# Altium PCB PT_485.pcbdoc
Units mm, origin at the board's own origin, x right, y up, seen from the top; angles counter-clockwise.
Board outline 61.6 x 60 mm, 2 copper layers (Top Layer, Bottom Layer); 37 components, 24 nets, 93 pads, 62 vias.
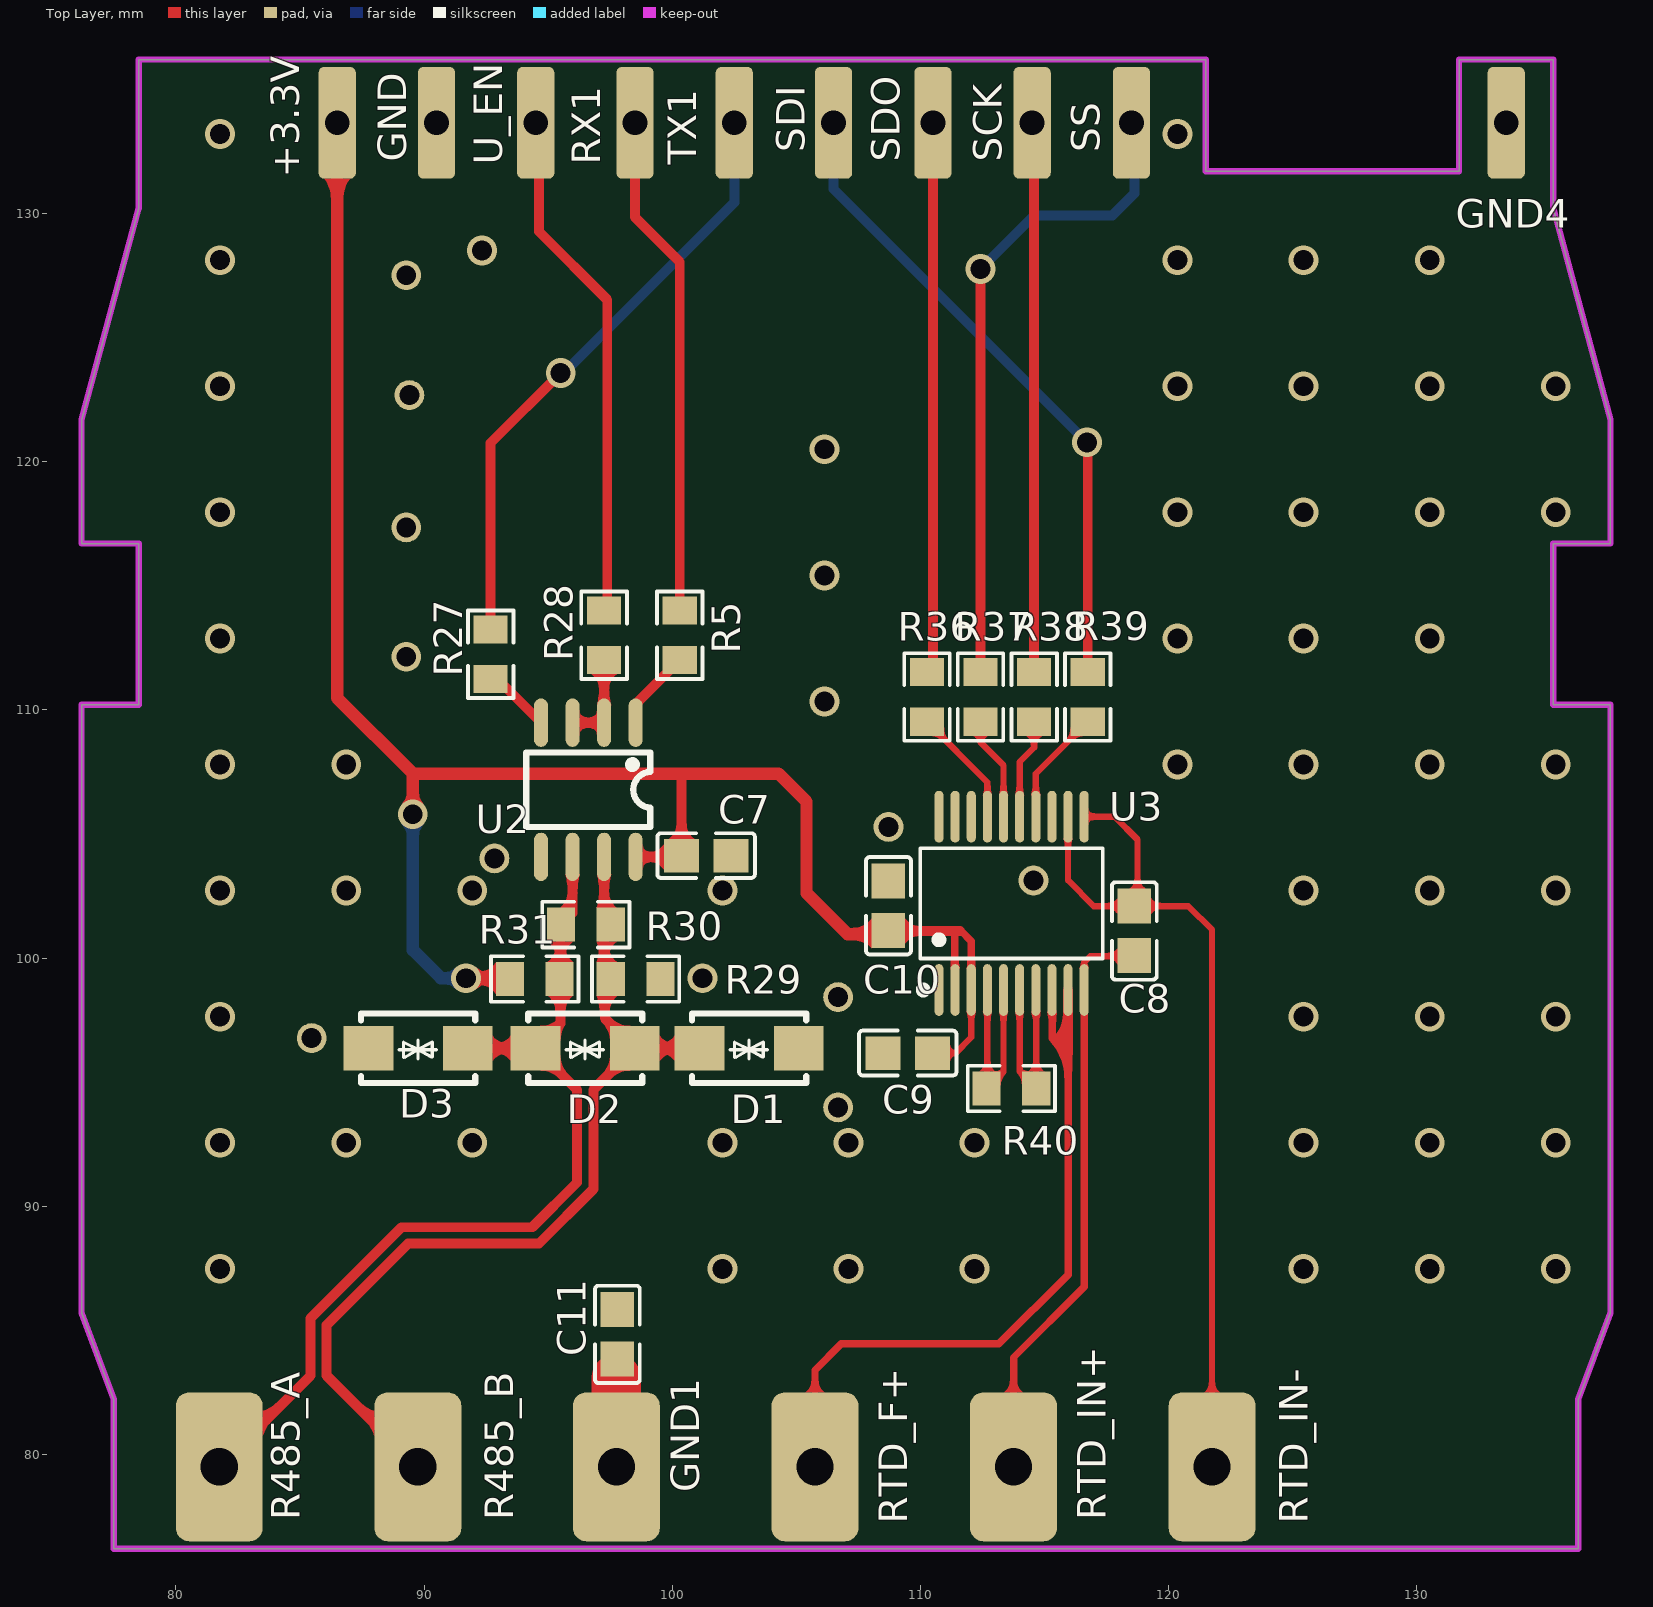
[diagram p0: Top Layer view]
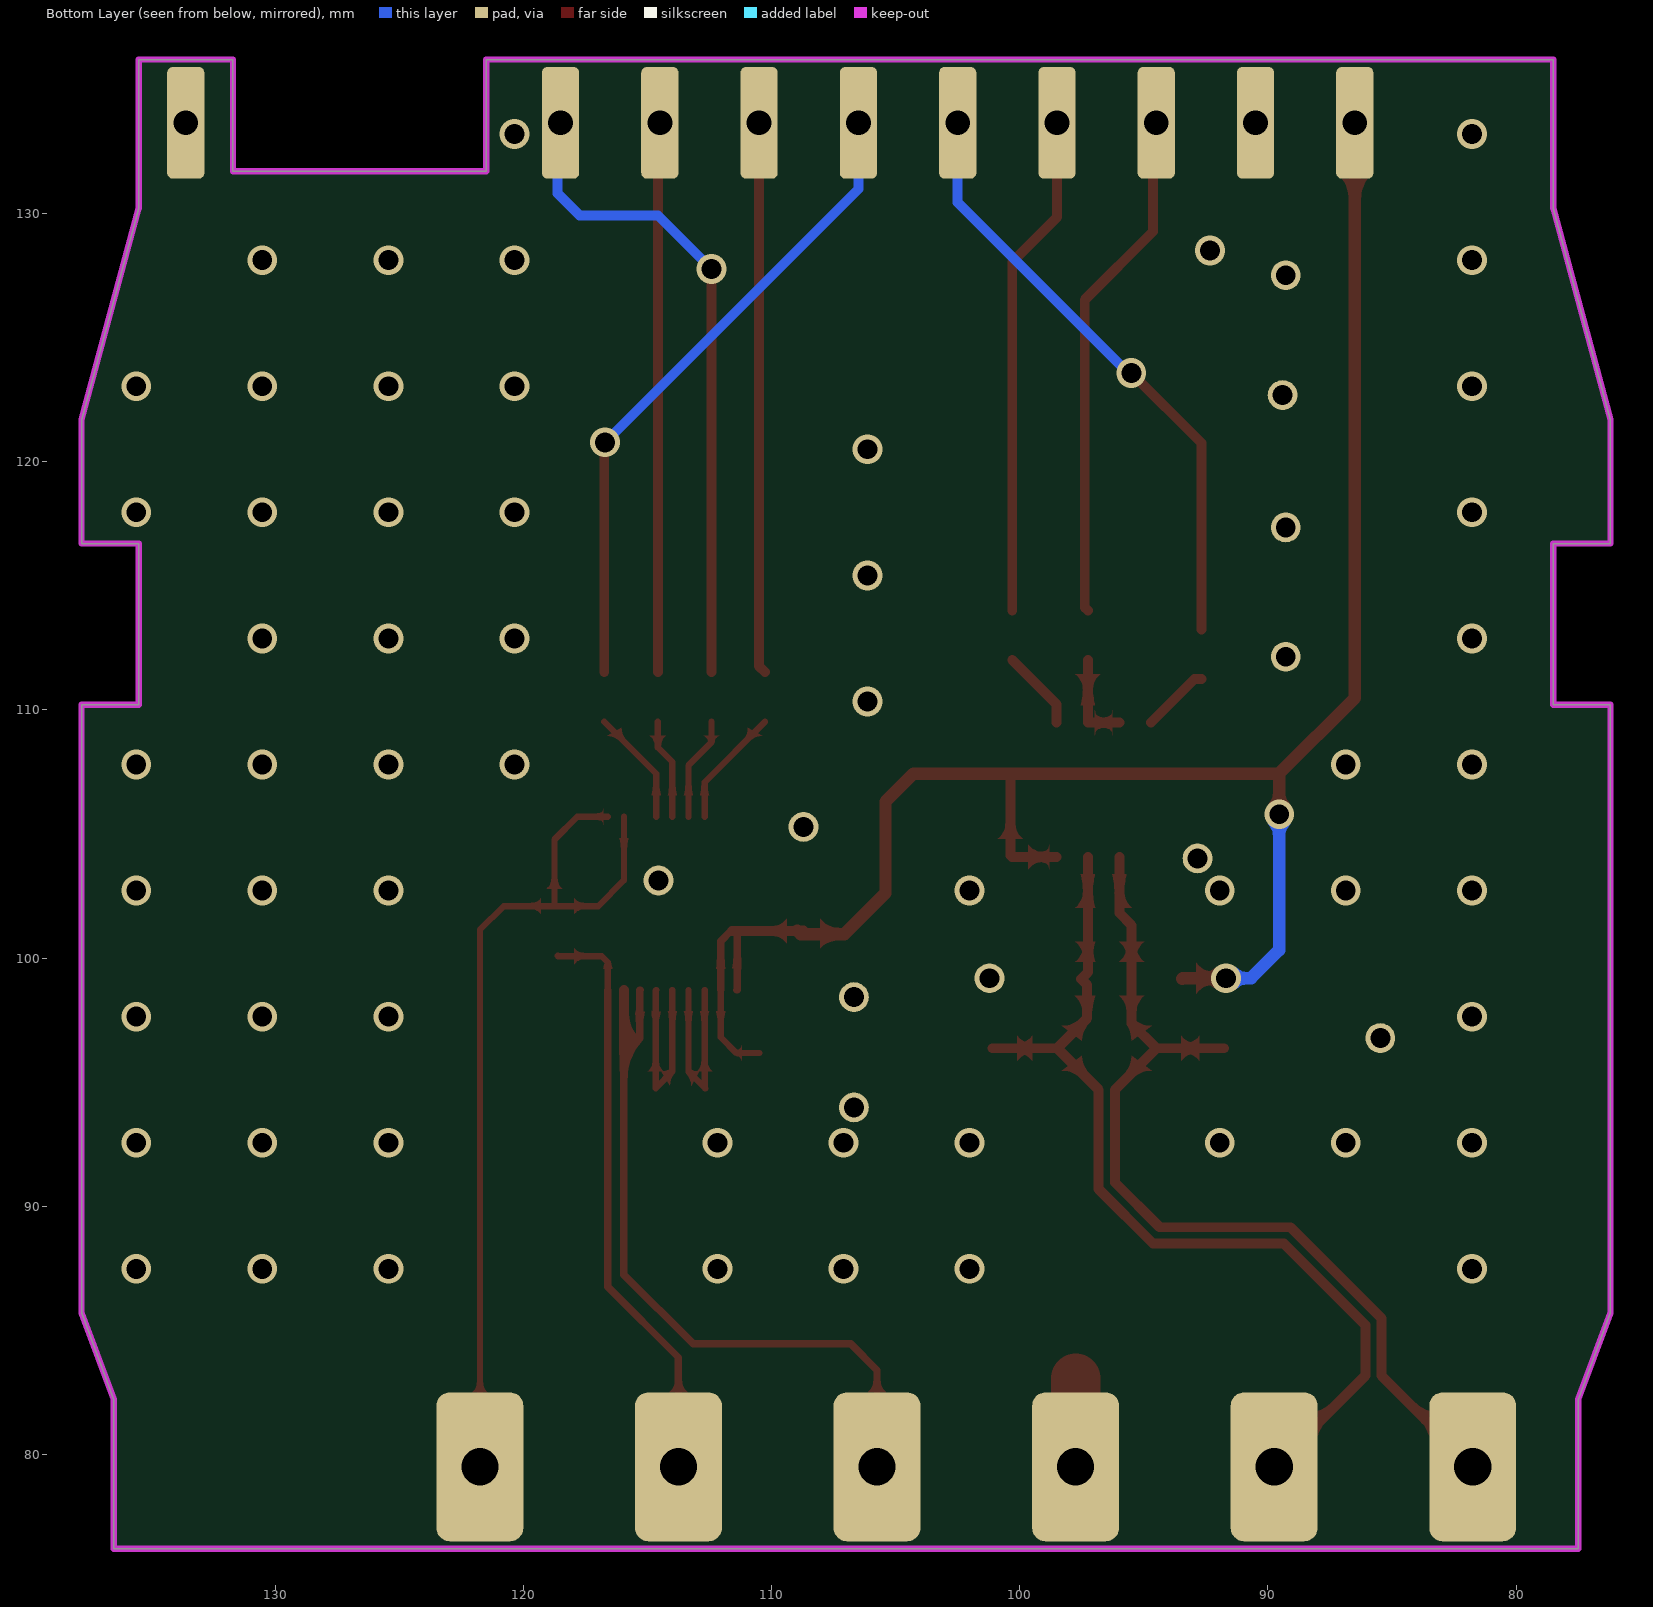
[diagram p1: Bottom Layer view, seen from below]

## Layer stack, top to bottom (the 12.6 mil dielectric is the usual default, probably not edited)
Top Layer: signal copper (thickness not stored)
Dielectric: dielectric 0.32, FR-4, Dk 4.8
Bottom Layer: signal copper (thickness not stored)

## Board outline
121.5,136.2 78.5,136.2 78.5,130.2 76.2,121.7 76.2,116.7 78.5,116.7 78.5,110.2 76.2,110.2 76.2,85.7 77.5,82.2 77.5,76.2 136.5,76.2 136.5,82.2 137.8,85.7 137.8,110.2 135.5,110.2 135.5,116.7 137.8,116.7 137.8,121.7 135.5,130.2 135.5,136.2 131.7,136.2 131.7,131.7 121.5,131.7

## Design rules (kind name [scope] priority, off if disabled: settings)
BoardOutlineClearance copperThickness1oz [All] p0: genericclearance=0.254 ignorepadtopadclearanceinfootprint=FALSE except(0: Arc-SplitContinuation Track-SplitContinuation SMDPad-SplitContinuation THPad-SplitContinuation Via-SplitContinuation Fill-SplitContinuation Poly-SplitContinuation Region-SplitContinuation Text-SplitContinuation; 0.203: SMDPad-OutlineEdge THPad-OutlineEdge Via-OutlineEdge; 0.254: Track-CutoutEdge SMDPad-CutoutEdge THPad-CutoutEdge Via-CutoutEdge Fill-CutoutEdge Region-CutoutEdge; 0.305: Track-OutlineEdge Fill-OutlineEdge Region-OutlineEdge Poly-OutlineEdge Text-OutlineEdge)
BoardOutlineClearance copperThickness2oz [All] p0: genericclearance=0.254 ignorepadtopadclearanceinfootprint=FALSE except(0: Arc-SplitContinuation Track-SplitContinuation SMDPad-SplitContinuation THPad-SplitContinuation Via-SplitContinuation Fill-SplitContinuation Poly-SplitContinuation Region-SplitContinuation Text-SplitContinuation; 0.152: Track-CutoutEdge SMDPad-CutoutEdge THPad-CutoutEdge Via-CutoutEdge Region-CutoutEdge; 0.3: Track-OutlineEdge SMDPad-OutlineEdge THPad-OutlineEdge Via-OutlineEdge Fill-OutlineEdge Region-OutlineEdge Poly-OutlineEdge Text-OutlineEdge Fill-CutoutEdge)
Clearance copperThickness1oz [(InNet('+3.3V') OR InNet('GND') OR InNet('RTD_IN+') OR InNet('R485_B') OR InNet('R485_A') OR InNet('$3N638') OR InNet('U1_RX') OR InNet('$3N640') OR InNet('U1_TX') OR InNet('$3N639') OR InNet('U1_EN') OR InNet('$2N377') OR InNet('SDO') OR InNet('$2N381') OR InNet('SS') OR InNet('$2N386') OR InNet('SCLK') OR InNet('$2N391') OR InNet('SDI') OR InNet('$2N592') OR InNet('$2N609') OR InNet('RTD_F+') OR InNet('RTD_F-') OR InNet('GND1'))] p1: gap=0.178 ignorepadtopadclearanceinfootprint=FALSE except(0.203: SMDPad-Sheet THPad-Sheet Via-Sheet; 0.254: Track-Track Track-SMDPad SMDPad-SMDPad Track-THPad SMDPad-THPad THPad-THPad Track-Via SMDPad-Via THPad-Via Via-Via SMDPad-Fill THPad-Fill Via-Fill Fill-Fill Track-Region SMDPad-Region THPad-Region Via-Region Fill-Region Region-Region Track-Poly SMDPad-Poly THPad-Poly Via-Poly Fill-Poly Region-Poly Poly-Poly Track-Text SMDPad-Text THPad-Text Via-Text Fill-Text Region-Text Poly-Text Text-Text Track-Hole SMDPad-Hole THPad-Hole Via-Hole Fill-Hole Region-Hole Poly-Hole Text-Hole Sheet-Hole; 0.305: Track-Fill Track-Sheet Fill-Sheet Region-Sheet Poly-Sheet Text-Sheet)
Clearance copperThickness2oz [All] p1: gap=0.178 ignorepadtopadclearanceinfootprint=FALSE except(0.152: Track-SMDPad SMDPad-SMDPad Track-THPad SMDPad-THPad THPad-THPad Track-Via SMDPad-Via THPad-Via Via-Via SMDPad-Fill THPad-Fill Via-Fill Fill-Fill Track-Region SMDPad-Region THPad-Region Via-Region Region-Region Track-Poly SMDPad-Poly THPad-Poly Via-Poly Fill-Poly Region-Poly Poly-Poly Track-Text SMDPad-Text THPad-Text Via-Text Fill-Text Region-Text Poly-Text Text-Text; 0.175: Track-Hole SMDPad-Hole THPad-Hole Via-Hole Fill-Hole Region-Hole Poly-Hole Text-Hole Sheet-Hole; 0.203: Track-Track; 0.3: Track-Fill Fill-Region Track-Sheet SMDPad-Sheet THPad-Sheet Via-Sheet Fill-Sheet Region-Sheet Poly-Sheet Text-Sheet)
DiffPairsRouting differentialPair [All] p1: maxuncoupledlength=10 minlimit=10 maxlimit=10 mostfreqgap=10 toplayer_minwidth=10 toplayer_prefwidth=15.748 toplayer_maxwidth=100 bottomlayer_minwidth=10 bottomlayer_prefwidth=15.748 bottomlayer_maxwidth=100
PasteMaskExpansion pasteMaskExpansion [All] p1: expansion=0
PlaneConnect innerPlane [All] p1: planeconnectstyle=Relief reliefexpansion=0.508 reliefentries=4 reliefconductorwidth=0.254 reliefairgap=0.254
PolygonConnect copperRegion [All] p1: connectstyle=Direct reliefentries=4 reliefconductorwidth=10 polygonreliefangle="90 Angle" airgapwidth=10
RoutingVias viaSize [All] p1: viastyle="Through Hole" holewidth=31.496 minholewidth=11.811 maxholewidth=247.9922 width=47.244 minwidth=19.685 maxwidth=393.7008
SolderMaskExpansion solderMaskExpansion [All] p1: useseparateexpansions=TRUE expansion=2.0079 expansionbottom=2.0079
Width copperThickness1oz [All] p1: maxlimit=100 minlimit=5 preferedwidth=10
Width copperThickness2oz [All] p1: maxlimit=100 minlimit=8 preferedwidth=10

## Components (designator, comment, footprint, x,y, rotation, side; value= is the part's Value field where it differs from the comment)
+3.3V "S_TM" S_FT 86.5,133.65 r0 top
C7 "CC0805KRX7R9BB104" C0805 101.366,104.128 r180 top
C8 "CC0805KRX7R9BB104" C0805 118.618,101.092 r90 top
C9 "CC0805KRX7R9BB104" C0805 109.49,96.171 r180 top
C10 "CC0805KRX7R9BB104" C0805 108.712,102.108 r90 top
C11 "0805B102K102CT" C0805 97.79,84.836 r90 top
D1 "SMAJ12CA_C152122" SMA_L4.4-W2.6-LS5.0-BI 103.096,96.365 r0 top
D2 "SMAJ12CA_C152122" SMA_L4.4-W2.6-LS5.0-BI 96.492,96.365 r0 top
D3 "SMAJ12CA_C152122" SMA_L4.4-W2.6-LS5.0-BI 89.761,96.365 r0 top
GND "S_TM" S_FT 90.5,133.65 r0 top
GND1 "B_TM" B_FT 97.75,79.5 r180 top
GND4 "S_TM" S_FT 133.6,133.65 r180 top
R5 "RC0805FR-071KL" R0805 100.302,113.002 r270 top
R27 "RC0805FR-071KL" R0805 92.682,112.24 r270 top
R28 "RC0805FR-071KL" R0805 97.254,113.002 r270 top
R29 "RC0805FR-074K7L" R0805 98.524,99.159 r0 top
R30 "RC0805FR-07120RL" R0805 96.52,101.346 r0 top
R31 "RC0805FR-074K7L" R0805 94.46,99.159 r0 top
R36 "RC0805JR-070RL" R0805 110.263,110.518 r270 top
R37 "RC0805JR-070RL" R0805 112.422,110.518 r270 top
R38 "RC0805JR-070RL" R0805 114.581,110.518 r270 top
R39 "RC0805JR-070RL" R0805 116.74,110.518 r270 top
R40 "TR0805B400RP0525Z" R0805 113.665,94.742 r180 top
R485_A "B_TM" B_FT 81.75,79.5 r180 top
R485_B "B_TM" B_FT 89.75,79.5 r180 top
RTD_F+ "B_TM" B_FT 105.75,79.5 r180 top
RTD_IN+ "B_TM" B_FT 113.75,79.5 r180 top
RTD_IN- "B_TM" B_FT 121.75,79.5 r180 top
RX1 "S_TM" S_FT 98.5,133.65 r180 top
SCK "S_TM" S_FT 114.5,133.65 r180 top
SDI "S_TM" S_FT 106.5,133.65 r180 top
SDO "S_TM" S_FT 110.5,133.65 r180 top
SS "S_TM" S_FT 118.5,133.65 r180 top
TX1 "S_TM" S_FT 102.5,133.65 r180 top
U2 "SP3485EN-L/TR" SOIC-8_L5.0-W4.0-P1.27-LS6.0-BL 96.619,106.779 r180 top
U3 "MAX31865AAP+T" SSOP-20_L7.2-W5.3-P0.65-LS7.8-BL 113.672,102.204 r0 top
U_EN "S_TM" S_FT 94.5,133.65 r180 top

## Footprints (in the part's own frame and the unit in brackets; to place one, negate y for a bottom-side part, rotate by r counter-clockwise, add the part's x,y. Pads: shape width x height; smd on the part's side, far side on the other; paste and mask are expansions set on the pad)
B_FT [mm]
  rrect30% 3.5x6 hole 1.5: 1(0,0)
C0805 [mm]
  rect 1.41x1.35 smd: 1(-1,0) 2(1,0)
  silkscreen extent -1.96,-0.9 1.96,0.9
R0805 [mm]
  rect 1.133x1.377 smd: 1(-1,0) 2(1,0)
  silkscreen extent -1.76,-0.92 1.76,0.92
S_FT [mm]
  rrect30% 1.5x4.5 hole 1: 1(0,0)
SMA_L4.4-W2.6-LS5.0-BI [mm]
  rect 2x1.8 smd: 1(-2,0) 2(2,0)
  silkscreen extent -2.3,-1.4 2.3,1.4
SOIC-8_L5.0-W4.0-P1.27-LS6.0-BL [mil]
  oval 22.38x76.78 smd: 1(-75,-106.5) 2(-25,-106.5) 3(25,-106.5) 4(75,-106.5) 5(75,106.5) 6(25,106.5) 7(-25,106.5) 8(-75,106.5)
  silkscreen extent -98,-59 98,59
SSOP-20_L7.2-W5.3-P0.65-LS7.8-BL [mm]
  oval 0.364x2.082 smd: 1(-2.925,-3.491) 2(-2.275,-3.491) 3(-1.625,-3.491) 4(-0.975,-3.491) 5(-0.325,-3.491) 6(0.325,-3.491) 7(0.975,-3.491) 8(1.625,-3.491) 9(2.275,-3.491) 10(2.925,-3.491) 11(2.925,3.491) 12(2.275,3.491) 13(1.625,3.491) 14(0.975,3.491) 15(0.325,3.491) 16(-0.325,3.491) 17(-0.975,3.491) 18(-1.625,3.491) 19(-2.275,3.491) 20(-2.925,3.491)
  silkscreen extent -3.71,-3.64 3.68,2.22

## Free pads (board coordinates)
  round 1.2 hole 0.8: 1(85.471,96.774) 1(89.281,112.141) 1(89.281,117.348) 1(89.281,127.508) 1(89.408,122.682) 1(92.837,104.013) 1(101.219,99.187) 1(106.68,93.98) 1(106.68,98.425) 1(108.712,105.283) 1(114.554,103.124)

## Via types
v1: diameter 1.2, hole 0.8, Top Layer to Bottom Layer, 62 vias

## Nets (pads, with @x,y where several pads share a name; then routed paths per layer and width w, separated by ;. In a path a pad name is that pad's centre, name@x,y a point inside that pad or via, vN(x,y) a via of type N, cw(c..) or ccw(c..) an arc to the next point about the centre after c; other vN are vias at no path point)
$2N377: R36.2 U3.17 | length 4.8
  Top Layer w0.254: R36.2 112.696,107.084 U3.17
$2N381: R37.2 U3.16 | length 4.2
  Top Layer w0.254: R37.2 112.422,108.685 113.347,107.76 U3.16
$2N386: R38.2 U3.15 | length 4.1
  Top Layer w0.254: U3.15 113.997,107.901 114.581,108.485 R38.2
$2N391: R39.2 U3.14 | length 4.7
  Top Layer w0.254: U3.14 114.647,107.425 R39.2
$2N592: R40.2 U3.4 U3.5 | length 8.2
  Top Layer w0.254: R40.2 R40.2@112.696,94.773 ; U3.4 R40.2@112.696,94.773 ; U3.5 113.347,95.424 R40.2@112.696,94.773
$2N609: R40.1 U3.6 U3.7 | length 8.2
  Top Layer w0.254: U3.6 113.997,95.426 114.665,94.758 114.665,98.694 U3.7
$3N638: R5.2 U2.1 | length 3.3
  Top Layer w0.4: U2.1 98.524,110.224 R5.2
$3N639: R28.2 U2.2 U2.3 | length 3.8
  Top Layer w0.4: U2.3 U2.2 R28.2
$3N640: R27.2 U2.4 | length 2.8
  Top Layer w0.4: R27.2 92.958,111.24 U2.4
+3.3V: +3.3V.1 C7.2 C9.1 C10.1 R31.1 U2.8 U3.2 U3.3 | length 80.1
  Top Layer w0.254: C9.1 111.411,96.171 112.046,96.806 U3.3
  Top Layer w0.3: 111.379,101.108 111.379,101.089 111.379,98.73 U3.2 ; 111.617,101.108 112.046,100.679 U3.3
  Top Layer w0.4: U2.8 100.312,104.074 C7.2 100.377,104.139 100.377,107.43 ; C10.1 108.966,101.108 108.985,101.089 111.379,101.089 111.598,101.089
  Top Layer w0.5: +3.3V.1 86.5,110.477 89.547,107.43 ; v1(89.547,105.791) 89.547,107.43 ; v1(91.694,99.187) 93.432,99.187 R31.1 ; C10.1@108.966,101.108 108.823,100.965 107.061,100.965 105.41,102.616 105.41,106.299 104.279,107.43 100.377,107.43 89.547,107.43
  Bottom Layer w0.5: v1(89.547,105.791) 89.547,100.318 90.678,99.187 v1(91.694,99.187)
GND: C7.1 C9.2 C10.2 C11.2 D1.2 D3.1 GND4.1 GND.1 pad.1 R29.2 U2.5 U3.13 U3.18 U3.19 U3.20
  other v1: 81.784,87.478 102.021,87.478 107.101,87.478 112.181,87.478 125.438,87.478 130.518,87.478 135.598,87.478 81.784,92.558 86.864,92.558 91.944,92.558 102.021,92.558 107.101,92.558 112.181,92.558 125.438,92.558 130.518,92.558 135.598,92.558 81.784,97.638 125.438,97.638 130.518,97.638 135.598,97.638 81.784,102.718 86.864,102.718 91.944,102.718 102.021,102.718 125.438,102.718 130.518,102.718 135.598,102.718 81.784,107.798 86.864,107.798 120.358,107.798 125.438,107.798 130.518,107.798 135.598,107.798 106.136,110.336 81.784,112.878 120.358,112.878 125.438,112.878 130.518,112.878 106.136,115.416 81.784,117.958 120.358,117.958 125.438,117.958 130.518,117.958 135.598,117.958 106.136,120.496 81.784,123.038 120.358,123.038 125.438,123.038 130.518,123.038 135.598,123.038 81.784,128.118 120.358,128.118 125.438,128.118 130.518,128.118 92.334,128.504 81.784,133.198 120.358,133.198
GND1: C11.1 GND1.1 | length 3.6
  Top Layer w2: GND1.1 97.75,83.058
R485_A: D2.1 D3.2 R30.1 R31.2 R485_A.1 U2.6 | length 37.7
  Top Layer w0.4: R485_A.1 85.423,83.173 85.423,85.488 89.089,89.154 94.361,89.154 96.165,90.958 96.165,94.692 D2.1 ; D3.2 D2.1 ; U2.6 95.984,101.81 95.492,101.318 95.492,97.365 D2.1
R485_B: D1.1 D2.2 R29.1 R30.2 R485_B.1 U2.7 | length 37.6
  Top Layer w0.4: R485_B.1 86.077,83.173 86.077,85.217 89.36,88.5 94.632,88.5 96.819,90.687 96.819,94.692 D2.2 ; U2.7 97.254,99.429 R29.1 97.282,98.917 97.282,97.575 D2.2 ; D1.1 D2.2
RTD_F+: RTD_F+.1 U3.8 U3.9 | length 30
  Top Layer w0.3: RTD_F+.1 105.75,83.398 106.807,84.455 113.157,84.455 115.947,87.245 115.947,96.143 115.316,96.774 115.316,98.693 U3.8
  Top Layer w0.4: 115.947,96.143 U3.9
RTD_F-: C8.2 RTD_IN-.1 U3.11 U3.12 | length 35.9
  Top Layer w0.254: U3.12 115.947,103.128 116.983,102.092 C8.2 120.793,102.092 121.75,101.135 RTD_IN-.1 ; U3.11 117.825,105.695 118.745,104.775 C8.2@118.745,102.235
RTD_IN+: C8.1 RTD_IN+.1 U3.10 | length 23.6
  Top Layer w0.254: U3.10 116.597,99.833 116.84,100.076 118.602,100.076 C8.1
  Top Layer w0.3: RTD_IN+.1 113.75,83.905 116.597,86.752 U3.10
SCLK: R38.1 SCK.1 | length 22.2
  Top Layer w0.4: SCK.1 114.581,133.569 R38.1
SDI: R39.1 SDI.1 | length 26.4
  Top Layer w0.4: v1(116.713,120.777) 116.74,120.75 R39.1
  Bottom Layer w0.4: SDI.1 106.5,130.99 v1(116.713,120.777)
SDO: R36.1 SDO.1 | length 22.2
  Top Layer w0.4: R36.1 110.5,111.755 SDO.1
SS: R37.1 SS.1 | length 26.6
  Top Layer w0.4: R37.1 v1(112.422,127.762)
  Bottom Layer w0.4: v1(112.422,127.762) 114.581,129.921 117.729,129.921 118.618,130.81 118.618,133.532 SS.1
U1_EN: R28.1 U_EN.1 | length 20.9
  Top Layer w0.4: U_EN.1 94.627,133.523 94.627,129.274 97.381,126.52 97.381,114.129 R28.1
U1_RX: R5.1 RX1.1 | length 20.4
  Top Layer w0.4: RX1.1 98.5,129.846 100.302,128.044 R5.1
U1_TX: R27.1 TX1.1 | length 24.6
  Top Layer w0.4: R27.1 92.682,120.749 v1(95.504,123.571)
  Bottom Layer w0.4: v1(95.504,123.571) 95.631,123.571 102.5,130.44 TX1.1
pads on no net: U3.1

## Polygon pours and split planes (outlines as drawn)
GND on Top Layer (solid, remove dead copper, pour order 0): 76.2,116.7 78.5,116.7 78.5,110.2 76.2,110.2 76.2,85.151 137.8,85.151 137.8,110.2 135.5,110.2 135.5,116.7 137.8,116.7 137.8,121.7 135.5,130.2 135.5,136.2 131.7,136.2 131.7,131.7 121.5,131.7 121.5,136.2 78.5,136.2 78.5,130.2 76.2,121.7
GND on Bottom Layer (solid, remove dead copper, pour order 2): 76.2,116.7 78.5,116.7 78.5,110.2 76.2,110.2 76.2,85.151 137.8,85.151 137.8,110.2 135.5,110.2 135.5,116.7 137.8,116.7 137.8,121.7 135.5,130.2 135.5,136.2 131.7,136.2 131.7,131.7 121.5,131.7 121.5,136.2 78.5,136.2 78.5,130.2 76.2,121.7

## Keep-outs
Board Outline Layer:
  the board outline again, w0.254

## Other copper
Top Layer:
  region net +3.3V: 86.75,130.65 86.25,130.65 ccw(c85.09,130.65) 85.975,131.4 87.025,131.4 ccw(c87.91,130.65)
  region net +3.3V: 100.177,105.403 100.577,105.403 ccw(c101.327,105.403) 100.877,104.803 99.877,104.803 ccw(c99.427,105.403)
  region net +3.3V: 99.061,103.874 99.061,104.274 ccw(c99.061,105.024) 99.661,104.574 99.661,103.574 ccw(c99.061,103.124)
  region net RTD_F-: 117.562,101.965 117.562,102.219 ccw(c117.562,102.695) 117.943,102.409 117.943,101.774 ccw(c117.562,101.489)
  region net RTD_F-: 118.618,103.178 118.872,103.178 ccw(c119.348,103.178) 119.062,102.797 118.427,102.797 ccw(c118.142,103.178)
  region net RTD_F-: 119.674,102.219 119.674,101.965 ccw(c119.674,101.489) 119.293,101.774 119.293,102.409 ccw(c119.674,102.695)
  region net RTD_IN+: 117.562,99.949 117.562,100.203 ccw(c117.562,100.679) 117.943,100.393 117.943,99.758 ccw(c117.562,99.473)
  region net +3.3V: 111.411,96.298 111.411,96.044 ccw(c111.411,95.826) 111.195,95.854 111.195,96.489 ccw(c111.411,96.516)
  region net +3.3V: 107.287,100.715 107.287,101.215 ccw(c107.287,102.152) 108.037,101.59 108.037,100.403 ccw(c107.287,99.658)
  region net +3.3V: 109.987,101.289 109.987,100.889 ccw(c109.987,100.139) 109.387,100.589 109.387,101.589 ccw(c109.987,102.039)
  region net R485_B: 99.496,96.165 99.496,96.565 ccw(c99.496,97.315) 100.096,96.865 100.096,95.865 ccw(c99.496,95.415)
  region net R485_A: 95.321,97.477 95.633,97.223 ccw(c96.694,96.658) 95.492,96.658 94.685,97.265 ccw(c94.685,98.325)
  region net R485_A: 95.704,95.436 95.321,95.253 ccw(c94.685,94.404) 94.685,95.465 95.492,96.072 ccw(c96.552,96.072)
  region net R485_A: 92.892,96.165 92.892,96.565 ccw(c92.892,97.315) 93.492,96.865 93.492,95.865 ccw(c92.892,95.415)
  region net R485_B: 97.28,97.294 97.663,97.477 ccw(c98.299,98.325) 98.299,97.265 97.492,96.658 ccw(c96.431,96.658)
  region net R485_B: 97.663,95.253 97.28,95.436 ccw(c96.431,96.072) 97.492,96.072 98.299,95.465 ccw(c98.299,94.404)
  region net R485_B: 100.092,96.565 100.092,96.165 ccw(c100.092,95.415) 99.492,95.865 99.492,96.865 ccw(c100.092,97.315)
  region net R485_A: 93.361,96.565 93.361,96.165 ccw(c93.361,95.415) 92.761,95.865 92.761,96.865 ccw(c93.361,97.315)
  region net $3N639: 97.454,110.836 97.054,110.836 ccw(c96.304,110.836) 96.754,111.436 97.754,111.436 ccw(c98.204,110.836)
  region net R485_B: 97.482,97.87 97.082,97.87 ccw(c95.573,97.87) 96.958,98.47 97.782,98.47 ccw(c98.232,97.87)
  region net R485_B: 97.054,100.447 97.454,100.447 ccw(c98.204,100.447) 97.754,99.847 96.958,99.847 ccw(c95.136,100.447)
  region net R485_B: 97.054,102.635 97.454,102.635 ccw(c98.204,102.635) 97.754,102.035 96.954,102.035 ccw(c95.206,102.635)
  region net R485_B: 97.454,100.057 97.054,100.057 ccw(c95.206,100.057) 96.954,100.657 97.754,100.657 ccw(c98.204,100.057)
  region net R485_A: 95.692,100.057 95.292,100.057 ccw(c94.542,100.057) 94.992,100.657 95.992,100.657 ccw(c96.442,100.057)
  region net R485_A: 95.784,102.635 96.184,102.635 ccw(c97.98,102.035) 96.086,102.035 95.484,102.035 ccw(c95.034,102.635)
  region net R485_A: 95.692,97.87 95.292,97.87 ccw(c94.542,97.87) 94.992,98.47 95.992,98.47 ccw(c96.442,97.87)
  region net R485_A: 95.292,100.447 95.692,100.447 ccw(c96.442,100.447) 95.992,99.847 94.992,99.847 ccw(c94.542,100.447)
  region net +3.3V: 92.144,98.937 92.144,99.437 ccw(c92.144,100.374) 92.894,99.812 92.894,98.562 ccw(c92.144,98)
  region net $2N377: 111.086,108.874 110.784,108.817 ccw(c110.38,108.278) 110.38,108.951 110.951,109.278 ccw(c111.625,109.278)
  region net $2N381: 112.549,108.685 112.295,108.685 ccw(c112.014,108.685) 112.104,108.951 112.739,108.951 ccw(c112.829,108.685)
  region net $2N386: 114.708,108.57 114.454,108.57 ccw(c113.977,108.57) 114.263,108.951 114.898,108.951 ccw(c115.184,108.57)
  region net $2N391: 116.218,108.817 115.916,108.874 ccw(c115.378,109.278) 116.051,109.278 116.622,108.951 ccw(c116.622,108.278)
  region net $2N592: 112.569,95.812 112.823,95.812 ccw(c113.3,95.812) 113.014,95.431 112.379,95.431 ccw(c112.093,95.812)
  region net $2N592: 113.257,95.513 113.366,95.263 ccw(c113.905,94.859) 113.231,94.859 112.904,95.431 ccw(c112.904,96.22)
  region net $2N609: 114.538,95.812 114.792,95.812 ccw(c115.268,95.812) 114.982,95.431 114.347,95.431 ccw(c114.062,95.812)
  region net $2N609: 113.964,95.279 114.086,95.516 ccw(c114.442,96.209) 114.442,95.431 114.099,94.875 ccw(c113.425,94.875)
  region net R485_A: 84.033,82.066 83.816,81.283 ccw(c84.699,80.4) 83.5,80.75 83.5,81.75 ccw(c83.15,82.949)
  region net R485_B: 87.684,81.283 87.467,82.066 ccw(c88.35,82.949) 88,81.75 88,80.75 ccw(c86.801,80.4)
  region net RTD_F+: 105.6,82.95 105.9,82.95 ccw(c106.462,82.95) 106.125,82.5 105.375,82.5 ccw(c105.038,82.95)
  region net RTD_IN+: 113.6,82.95 113.9,82.95 ccw(c114.462,82.95) 114.125,82.5 113.375,82.5 ccw(c113.038,82.95)
  region net RTD_F-: 121.623,82.881 121.877,82.881 ccw(c122.353,82.881) 122.068,82.5 121.433,82.5 ccw(c121.147,82.881)
  region net $3N639: 96.37,109.284 96.37,109.684 96.482,109.685 96.59,109.689 96.691,109.7 96.738,109.709 96.782,109.721 96.822,109.737 96.859,109.757 96.891,109.781 96.918,109.81 96.94,109.845 96.956,109.885 96.966,109.931 96.97,109.984 96.97,108.984 96.966,109.037 96.956,109.083 96.94,109.123 96.918,109.157 96.891,109.186 96.859,109.211 96.822,109.231 96.782,109.246 96.738,109.259 96.691,109.268 96.59,109.279 96.482,109.283
  region net $3N639: 97.054,110.775 97.454,110.775 97.457,110.664 97.467,110.558 97.48,110.46 97.496,110.372 97.525,110.237 97.538,110.175 96.97,110.175 96.983,110.237 97.012,110.372 97.027,110.46 97.041,110.558 97.05,110.664
  region net $3N639: 96.868,109.684 96.868,109.284 96.756,109.283 96.648,109.279 96.546,109.268 96.499,109.259 96.456,109.246 96.415,109.231 96.379,109.211 96.347,109.186 96.32,109.157 96.298,109.123 96.282,109.083 96.271,109.037 96.268,108.984 96.268,109.984 96.271,109.931 96.282,109.885 96.298,109.845 96.32,109.81 96.347,109.781 96.379,109.757 96.415,109.737 96.456,109.721 96.499,109.709 96.546,109.7 96.648,109.689 96.756,109.685
  region net +3.3V: 99.408,104.274 99.408,103.874 99.296,103.873 99.188,103.869 99.086,103.858 99.039,103.849 98.996,103.836 98.955,103.82 98.919,103.8 98.887,103.776 98.86,103.747 98.838,103.713 98.822,103.673 98.811,103.627 98.808,103.574 98.808,104.574 98.811,104.521 98.822,104.475 98.838,104.435 98.86,104.4 98.887,104.371 98.919,104.347 98.955,104.327 98.996,104.311 99.039,104.299 99.086,104.29 99.188,104.278 99.296,104.274
  region net R485_B: 97.454,102.783 97.054,102.783 97.05,102.894 97.041,103 97.027,103.098 97.012,103.186 96.983,103.321 96.97,103.383 97.538,103.383 97.525,103.321 97.496,103.186 97.48,103.098 97.467,103 97.457,102.894
  region net R485_A: 96.184,102.783 95.784,102.783 95.78,102.894 95.771,103 95.757,103.098 95.742,103.186 95.713,103.321 95.7,103.383 96.268,103.383 96.255,103.321 96.226,103.186 96.21,103.098 96.197,103 96.187,102.894
  region net +3.3V: 111.229,100.004 111.529,100.039 111.535,99.933 111.549,99.814 111.578,99.589 111.215,99.554 111.211,99.666 111.217,99.779 111.225,99.892
  region net +3.3V: 112.173,97.473 111.919,97.473 111.917,97.543 111.911,97.609 111.892,97.725 111.873,97.81 111.864,97.854 112.228,97.854 112.22,97.81 112.201,97.725 112.182,97.609 112.176,97.543
  region net +3.3V: 111.896,100.022 112.196,100.022 112.201,99.86 112.212,99.722 112.228,99.572 111.864,99.572 111.88,99.722 111.891,99.86
  region net $2N592: 112.823,97.473 112.569,97.473 112.567,97.543 112.561,97.609 112.542,97.725 112.523,97.81 112.514,97.854 112.878,97.854 112.87,97.81 112.851,97.725 112.832,97.609 112.826,97.543
  region net $2N592: 113.474,97.473 113.22,97.473 113.217,97.543 113.211,97.609 113.192,97.725 113.173,97.81 113.165,97.854 113.529,97.854 113.52,97.81 113.501,97.725 113.482,97.609 113.476,97.543
  region net $2N609: 114.124,97.473 113.87,97.473 113.867,97.543 113.861,97.609 113.842,97.725 113.823,97.81 113.815,97.854 114.179,97.854 114.17,97.81 114.151,97.725 114.132,97.609 114.126,97.543
  region net $2N609: 114.792,97.491 114.538,97.454 114.536,97.515 114.529,97.565 114.509,97.645 114.485,97.726 114.474,97.775 114.466,97.835 114.828,97.872 114.832,97.811 114.83,97.761 114.817,97.682 114.8,97.602 114.794,97.553
  region net RTD_F+: 115.466,97.423 115.166,97.384 115.16,97.488 115.146,97.61 115.116,97.834 115.478,97.873 115.482,97.764 115.477,97.648 115.47,97.533
  region net RTD_IN+: 116.47,99.833 116.724,99.833 116.726,99.785 116.732,99.74 116.751,99.663 116.77,99.605 116.779,99.572 116.415,99.572 116.423,99.605 116.442,99.663 116.461,99.74 116.467,99.785
  region net $2N377: 112.569,106.935 112.823,106.935 112.826,106.865 112.832,106.798 112.851,106.682 112.87,106.597 112.878,106.554 112.514,106.554 112.523,106.597 112.542,106.682 112.561,106.798 112.567,106.865
  region net $2N381: 113.22,106.935 113.474,106.935 113.476,106.865 113.482,106.798 113.501,106.682 113.52,106.597 113.529,106.554 113.165,106.554 113.173,106.597 113.192,106.682 113.211,106.798 113.217,106.865
  region net $2N386: 113.87,106.935 114.124,106.935 114.126,106.865 114.132,106.798 114.151,106.682 114.17,106.597 114.179,106.554 113.815,106.554 113.823,106.597 113.842,106.682 113.861,106.798 113.867,106.865
  region net $2N391: 114.52,106.935 114.774,106.935 114.776,106.865 114.782,106.798 114.801,106.682 114.82,106.597 114.829,106.554 114.465,106.554 114.473,106.597 114.492,106.682 114.511,106.798 114.517,106.865
  region net RTD_F-: 116.074,104.455 115.82,104.455 115.817,104.525 115.811,104.591 115.792,104.707 115.773,104.792 115.765,104.836 116.129,104.836 116.12,104.792 116.101,104.707 116.082,104.591 116.076,104.525
  region net RTD_F-: 117.16,105.822 117.16,105.568 117.02,105.565 116.955,105.558 116.898,105.544 116.849,105.521 116.829,105.506 116.811,105.487 116.797,105.466 116.787,105.44 116.781,105.411 116.779,105.377 116.779,106.012 116.781,105.979 116.787,105.949 116.797,105.924 116.811,105.902 116.829,105.884 116.849,105.868 116.898,105.846 116.955,105.832 117.02,105.825
  region net +3.3V: 89.297,106.608 89.797,106.608 89.802,106.551 89.814,106.494 89.834,106.438 89.86,106.384 89.89,106.331 89.924,106.28 89.997,106.188 89.097,106.188 89.171,106.28 89.204,106.331 89.235,106.384 89.26,106.438 89.28,106.494 89.293,106.551
  region net +3.3V: 92.511,99.437 92.511,98.937 92.454,98.933 92.397,98.92 92.341,98.9 92.287,98.875 92.234,98.844 92.183,98.81 92.091,98.737 92.091,99.637 92.183,99.564 92.234,99.53 92.287,99.499 92.341,99.474 92.397,99.454 92.454,99.441
  region net RTD_F+: 115.747,97.755 cw(c114.404,97.755) 115.422,96.88 115.21,96.668 cw(c113.62,95.181) 115.797,95.181 116.097,94.811 116.118,96.04
Bottom Layer:
  region net +3.3V: 89.797,104.974 89.297,104.974 89.293,105.031 89.28,105.088 89.26,105.144 89.235,105.198 89.204,105.251 89.171,105.302 89.097,105.394 89.997,105.394 89.924,105.302 89.89,105.251 89.86,105.198 89.834,105.144 89.814,105.088 89.802,105.031
  region net +3.3V: 90.877,98.937 90.877,99.437 90.934,99.441 90.991,99.454 91.047,99.474 91.101,99.499 91.154,99.53 91.205,99.564 91.297,99.637 91.297,98.737 91.205,98.81 91.154,98.844 91.101,98.875 91.047,98.9 90.991,98.92 90.934,98.933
